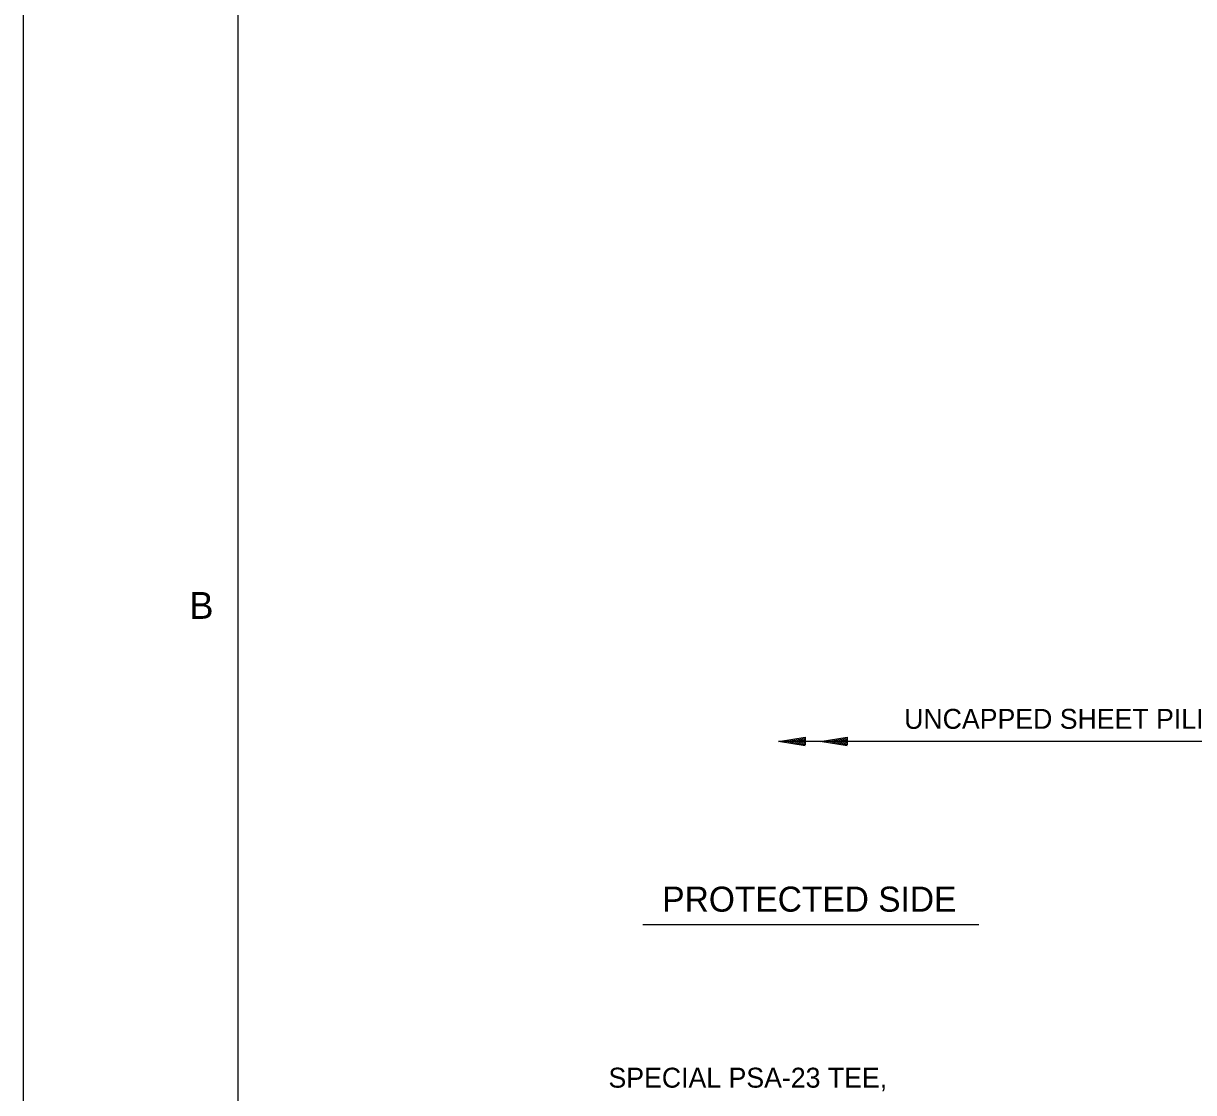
# Model space of a CAD drawing. Extents: x 22369.6 to 22428.3, y 22369.6 to 22415.
# Drawn here: x 22369.62 to 22380.52, y 22382.23 to 22392.19 of the extents above; entities that cross this region are included whole.
import ezdxf

# ---------------------------------------------------------------- set-up
doc = ezdxf.new("R2010")
doc.units = 0
for name, color, linetype in [('Level 1', 7, 'Continuous'), ('Level 10', 7, 'Continuous'), ('Level 4', 7, 'Continuous'), ('Level 9', 7, 'Continuous')]:
    doc.layers.add(name, color=color, linetype=linetype)

msp = doc.modelspace()

# ---------------------------------------------------------------- linework, layer by layer
at = {"layer": 'Level 1'}
for p, q in [((22377.28, 22385.53), (22377.28, 22385.53)), ((22377.29, 22385.543), (22377.29, 22385.543)), ((22382.078, 22385.502), (22376.652, 22385.502)), ((22376.652, 22385.502), (22376.652, 22385.502)), ((22376.721, 22385.502), (22376.721, 22385.502)), ((22377.246, 22385.502), (22377.246, 22385.502)), ((22377.269, 22385.517), (22377.269, 22385.517)), ((22377.269, 22385.498), (22377.269, 22385.498)), ((22377.28, 22385.485), (22377.28, 22385.485)), ((22377.29, 22385.473), (22377.29, 22385.473)), ((22377.29, 22385.461), (22377.29, 22385.461))]:
    msp.add_line(p, q, dxfattribs=at)
msp.add_lwpolyline([(22369.621, 22414.965), (22428.288, 22414.965), (22428.288, 22369.621), (22369.621, 22369.621)], close=True, dxfattribs=at)
for points in [[(22376.901, 22385.461), (22376.652, 22385.502), (22376.901, 22385.543), (22376.901, 22385.473), (22376.721, 22385.502), (22376.89, 22385.53), (22376.89, 22385.485), (22376.788, 22385.502), (22376.88, 22385.517), (22376.88, 22385.498), (22376.857, 22385.502)], [(22377.29, 22385.461), (22377.041, 22385.502), (22377.29, 22385.543), (22377.29, 22385.473), (22377.11, 22385.502), (22377.28, 22385.53), (22377.28, 22385.485), (22377.177, 22385.502), (22377.269, 22385.517), (22377.269, 22385.498), (22377.246, 22385.502)]]:
    msp.add_lwpolyline(points, dxfattribs=at)
at = {"layer": 'Level 10'}
msp.add_line((22375.389, 22383.798), (22378.517, 22383.798), dxfattribs=at)
at = {"layer": 'Level 9'}
msp.add_line((22371.621, 22370.293), (22371.621, 22414.293), dxfattribs=at)

# ---------------------------------------------------------------- texts
at = {"layer": 'Level 1'}
msp.add_text('B', height=0.25, dxfattribs=at).set_placement((22371.168, 22386.645))
at = {"layer": 'Level 10'}
msp.add_text('PROTECTED SIDE', height=0.23329, dxfattribs=at).set_placement((22375.57, 22383.918))
at = {"layer": 'Level 4'}
for s, p in [('UNCAPPED SHEET PILING', (22377.822, 22385.621)), ('SPECIAL PSA-23 TEE,', (22375.069, 22382.279))]:
    msp.add_text(s, height=0.1857, dxfattribs=at).set_placement(p)

doc.saveas('drawing.dxf')
